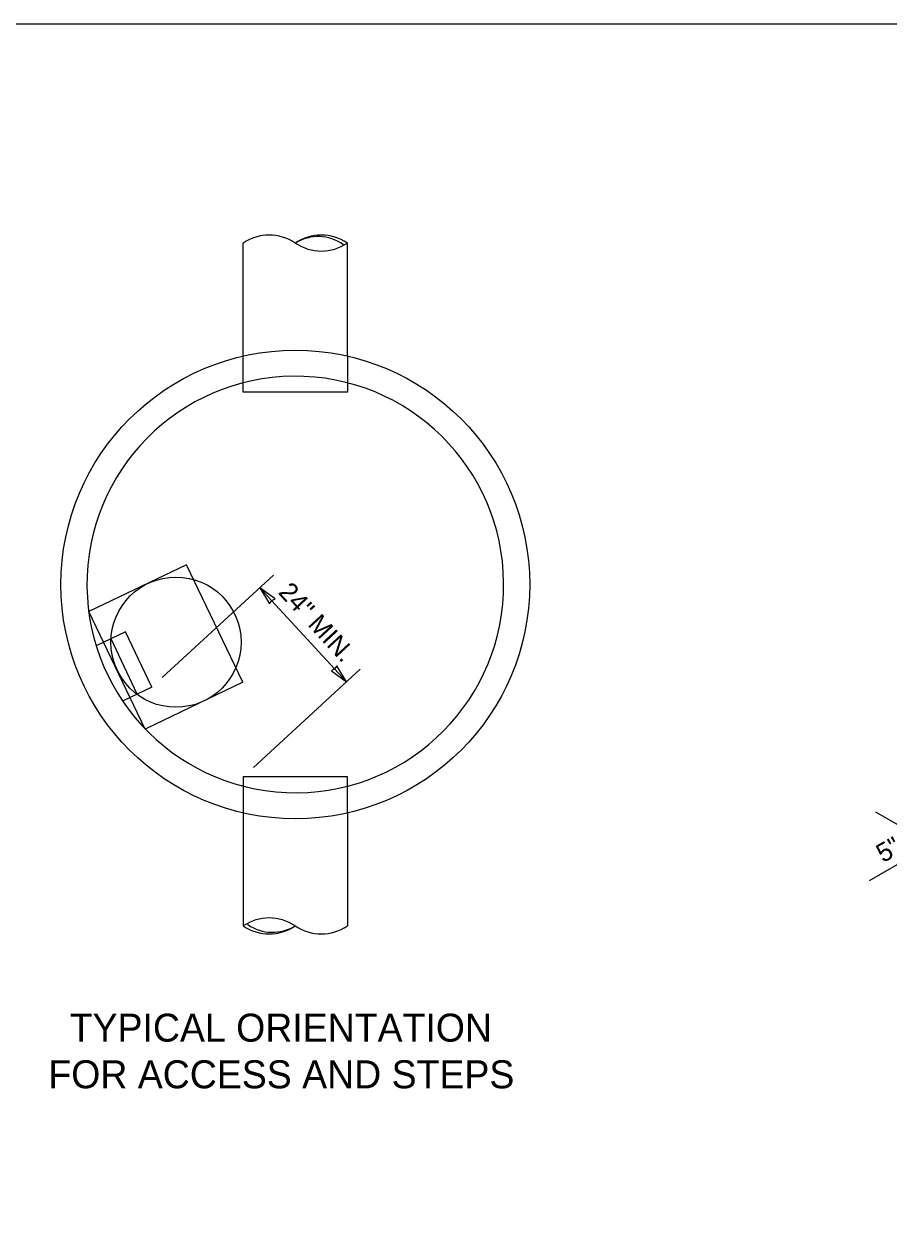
# Model space of a CAD drawing. Extents: x 99862 to 103151, y 100000 to 102076.
# Drawn here: x 100987 to 101728, y 101038 to 102076 of the extents above; entities that cross this region are included whole.
import ezdxf

# ---------------------------------------------------------------- set-up
doc = ezdxf.new("R2010")
doc.units = 0
for name, color, linetype in [('Level 1', 7, 'Continuous'), ('Level 15', 7, 'Continuous'), ('Level 17', 7, 'Continuous'), ('Level 18', 7, 'Continuous'), ('Level 20', 7, 'Continuous'), ('Level 6', 7, 'Continuous')]:
    doc.layers.add(name, color=color, linetype=linetype)

msp = doc.modelspace()

# ---------------------------------------------------------------- linework, layer by layer
at = {"layer": 'Level 1'}
msp.add_lwpolyline([(99862, 99999.5), (103151, 99999.5), (103151, 102075.5), (99862, 102075.5)], close=True, dxfattribs=at)
at = {"layer": 'Level 15'}
for p, q in [((101105.2, 101515.2), (101200.7, 101603.1)), ((101188.9, 101592.3), (101263.2, 101511.6)), ((101183.4, 101438.2), (101275, 101522.5)), ((101795.3, 101354.7), (101716.9, 101399.8)), ((101711.5, 101341.3), (101765, 101372.1))]:
    msp.add_line(p, q, dxfattribs=at)
for points in [[(101188.9, 101592.3), (101197.3, 101578.6), (101199.1, 101581.3), (101201.9, 101582.8)], [(101263.2, 101511.6), (101254.8, 101525.3), (101253, 101522.7), (101250.3, 101521.1)]]:
    msp.add_lwpolyline(points, close=True, dxfattribs=at)
at = {"layer": 'Level 17'}
for p, q in [((101126.1, 101611.9), (101042.2, 101571.9)), ((101174.4, 101511.2), (101126.1, 101611.9)), ((101090.5, 101471), (101042.2, 101571.9)), ((101174.4, 101511.2), (101090.5, 101471))]:
    msp.add_line(p, q, dxfattribs=at)
for centre, radius in [((101219.3, 101595.1), 200.9), ((101117, 101545.6), 55.8)]:
    msp.add_circle(centre, radius, dxfattribs=at)
msp.add_arc((101219.3, 101595.1), 178.6, 357.64, 357.5432, dxfattribs=at)
at = {"layer": 'Level 18'}
for p, q in [((101073.8, 101554.6), (101048.6, 101542.5)), ((101083.7, 101501.1), (101061.3, 101548.6)), ((101096.4, 101507.1), (101073.8, 101554.6)), ((101096.4, 101507.1), (101071.2, 101495))]:
    msp.add_line(p, q, dxfattribs=at)
at = {"layer": 'Level 6'}
for p, q in [((101174.6, 101791), (101174.6, 101887.8)), ((101263.9, 101791), (101263.9, 101887.8)), ((101174.6, 101399.2), (101174.6, 101302.3)), ((101263.9, 101399.2), (101263.9, 101302.3))]:
    msp.add_line(p, q, dxfattribs=at)
for points in [[(101263.9, 101791), (101263.9, 101760.1), (101174.6, 101760.1), (101174.6, 101791)], [(101263.9, 101399.2), (101263.9, 101430.1), (101174.6, 101430.1), (101174.6, 101399.2)]]:
    msp.add_lwpolyline(points, dxfattribs=at)
for centre, start, end in [((101259.7, 101885.8), 6.0383, 54.3821), ((101179.2, 101304.2), 165.307, 236.8734)]:
    msp.add_arc(centre, 1, start, end, dxfattribs=at)
for centre, major_axis, ratio, start_param, end_param in [((101196.9, 101843.5), (0, -51.2), 0.872704, 2.617994, 3.665191), ((101241.6, 101843.5), (0, -51.2), 0.872704, 2.617994, 3.665191), ((101238, 101845.3), (-4.1, -48), 0.864778, 2.677143, 3.703026), ((101241.6, 101932.2), (0, -51.2), 0.872704, 5.759587, 6.806784), ((101196.9, 101258), (0, 51.2), 0.872704, 5.759587, 6.806784), ((101196.9, 101346.7), (0, 51.2), 0.872704, 2.617994, 3.665191), ((101200.6, 101345), (4.1, 48), 0.864778, 2.686532, 3.702105), ((101241.6, 101346.7), (0, 51.2), 0.872704, 2.617994, 3.665191)]:
    msp.add_ellipse(centre, major_axis=major_axis, ratio=ratio, start_param=start_param, end_param=end_param, dxfattribs=at)

# ---------------------------------------------------------------- texts
at = {"layer": 'Level 20'}
for s, rotation, p in [('24" MIN.', 312.6314, (101204, 101587.8)), ('5"', 29.9987, (101723.2, 101356.1))]:
    msp.add_text(s, height=16, rotation=rotation, dxfattribs=at).set_placement(p)
for s, p in [('TYPICAL ORIENTATION', (101025.9, 101203.1)), ('FOR ACCESS AND STEPS', (101007.6, 101163.1))]:
    msp.add_text(s, height=24, dxfattribs=at).set_placement(p)

doc.saveas('drawing.dxf')
